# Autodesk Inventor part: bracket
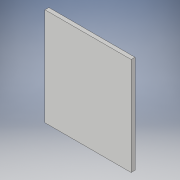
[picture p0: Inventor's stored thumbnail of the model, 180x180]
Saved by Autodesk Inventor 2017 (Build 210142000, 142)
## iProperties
Created: 2020-03
Part Number: bracket
Material: Generic
Document SubType Name: Modeling
Designer: user
Density: 1 g/cm^3
Appearance: Default
Author: user
Revision Number: ANY
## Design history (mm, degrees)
fillet "Fillet1"
sketch "Sketch1"
  geometry: L1 (44, 51.545)-(67.182, 51.545); L2 (67.182, 51.545)-(67.182, -9.997); L3 (67.182, -9.997)-(44, -9.997); L4 (44, -9.997)-(44, 51.545); 2 further points
  constraints: 8 end point, 2 parallel, 1 horizontal, 1 perpendicular, 1 point on line
extrude "Extrusion1" cut sketch "Sketch1" stored distance "d0" = 0; taper "d1" = 0 deg
body "Solid1"
